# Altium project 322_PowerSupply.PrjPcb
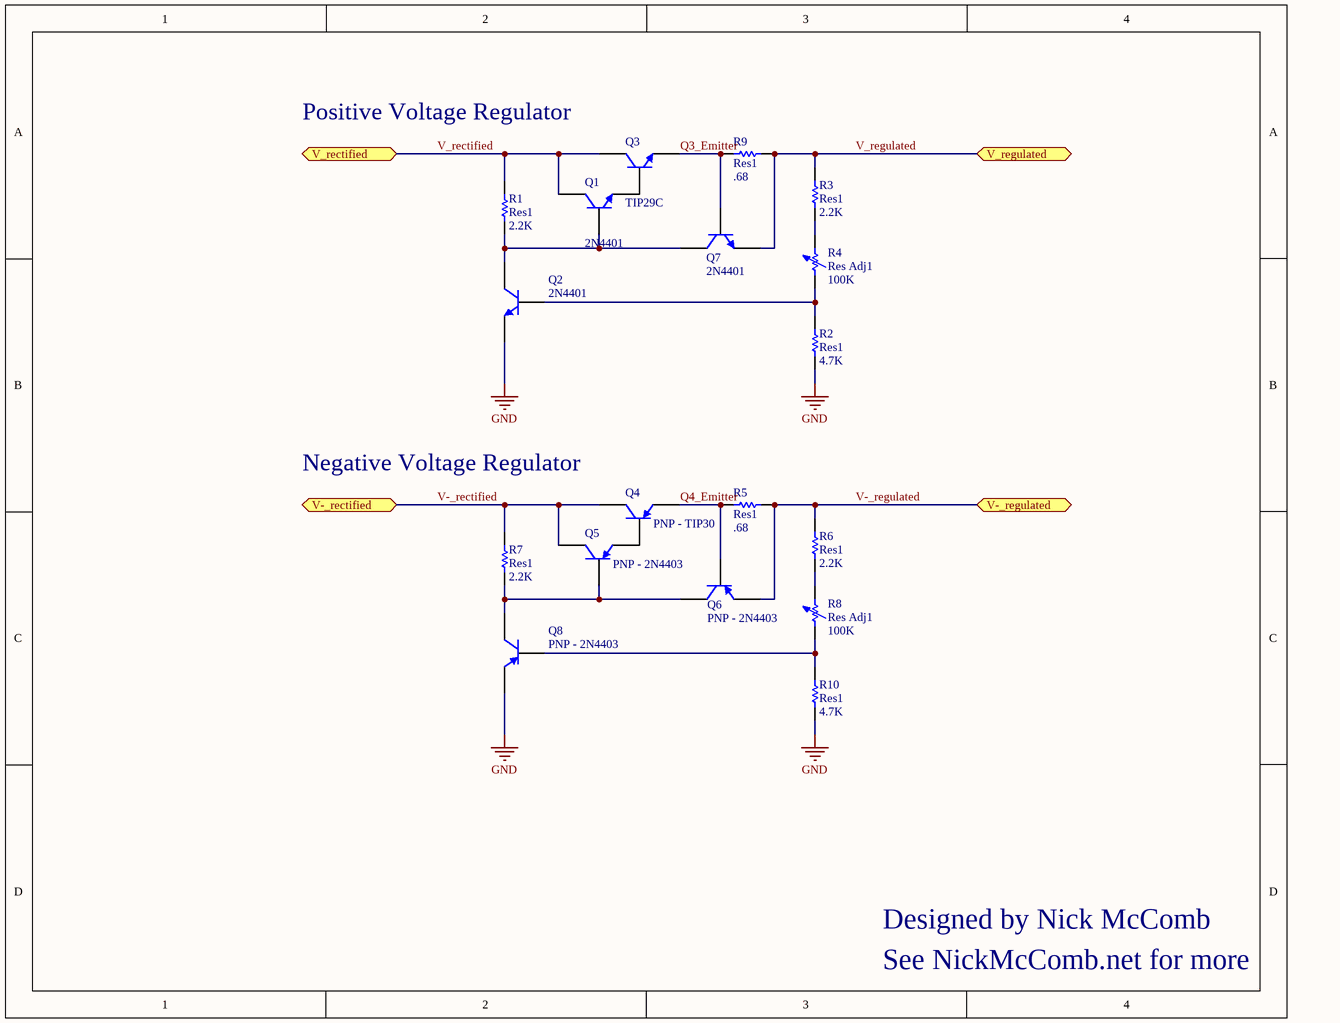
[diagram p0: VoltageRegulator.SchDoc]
2 sheets, 35 parts. Net scope: flat (ports and power ports of the same name join across sheets).
Board file: VoltageRegulator.PcbDoc
Sheets:
  VoltageRegulator.SchDoc
  Connectors.SchDoc

## Sheet VoltageRegulator.SchDoc
size A

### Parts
Q1  2N4401  [TO-92A - BJT]
Q2  2N4401  [TO-92A - BJT]
Q3  TIP29C  [TO-220AB]
Q4  PNP - TIP30  [TO-220AB]
Q5  PNP - 2N4403  [TO-92A - BJT]
Q6  PNP - 2N4403  [TO-92A - BJT]
Q7  2N4401  [TO-92A - BJT]
Q8  PNP - 2N4403  [TO-92A - BJT]
R1  Res1  value 2.2K  [AXIAL-0.3]
R2  Res1  value 4.7K  [AXIAL-0.3]
R3  Res1  value 2.2K  [AXIAL-0.3]
R4  Res Adj1  value 100K  [POT Connections]
R5  Res1  value .68  [AXIAL-0.4]
R6  Res1  value 2.2K  [AXIAL-0.3]
R7  Res1  value 2.2K  [AXIAL-0.3]
R8  Res Adj1  value 100K  [POT Connections]
R9  Res1  value .68  [AXIAL-0.4]
R10  Res1  value 4.7K  [AXIAL-0.3]

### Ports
V-_rectified, V-_regulated, V_rectified, V_regulated

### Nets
GND: Q2.3(E) Q8.3(E) R2.1 R10.1
Q3_Emitter: Q3.3(E) Q7.2(B) R9.1
Q4_Emitter: Q4.3(E) Q6.2(B) R5.1
V-_rectified: Q4.2(C) Q5.1(C) R7.2 ; port V-_rectified
V-_regulated: Q6.3(E) R5.2 R6.2 ; port V-_regulated
V_rectified: Q1.1(C) Q3.2(C) R1.2 ; port V_rectified
V_regulated: Q7.3(E) R3.2 R9.2 ; port V_regulated
NetQ1_2: Q1.2(B) Q2.1(C) Q7.1(C) R1.1
NetQ1_3: Q1.3(E) Q3.1(B)
NetQ2_2: Q2.2(B) R2.2 R4.1
NetQ4_1: Q4.1(B) Q5.3(E)
NetQ5_2: Q5.2(B) Q6.1(C) Q8.1(C) R7.1
NetQ8_2: Q8.2(B) R8.1 R10.2
NetR3_1: R3.1 R4.2
NetR6_1: R6.1 R8.2

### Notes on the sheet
- (near Q3) Positive Voltage Regulator
- (near Q4) Negative Voltage Regulator
- Designed by Nick McComb
- See NickMcComb.net for more

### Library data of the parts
Q1 Q2 Q7 = 2N4401: NPN General Purpose Amplifier
Q3 = TIP29C: NPN General Purpose Amplifier
Q4 = PNP - TIP30: PNP Bipolar Transistor
Q5 Q6 Q8 = PNP - 2N4403: PNP Bipolar Transistor
R1-R3 R5-R7 R9 R10 = Res1: Resistor
R4 R8 = Res Adj1: Variable Resistor

## Sheet Connectors.SchDoc
size A4
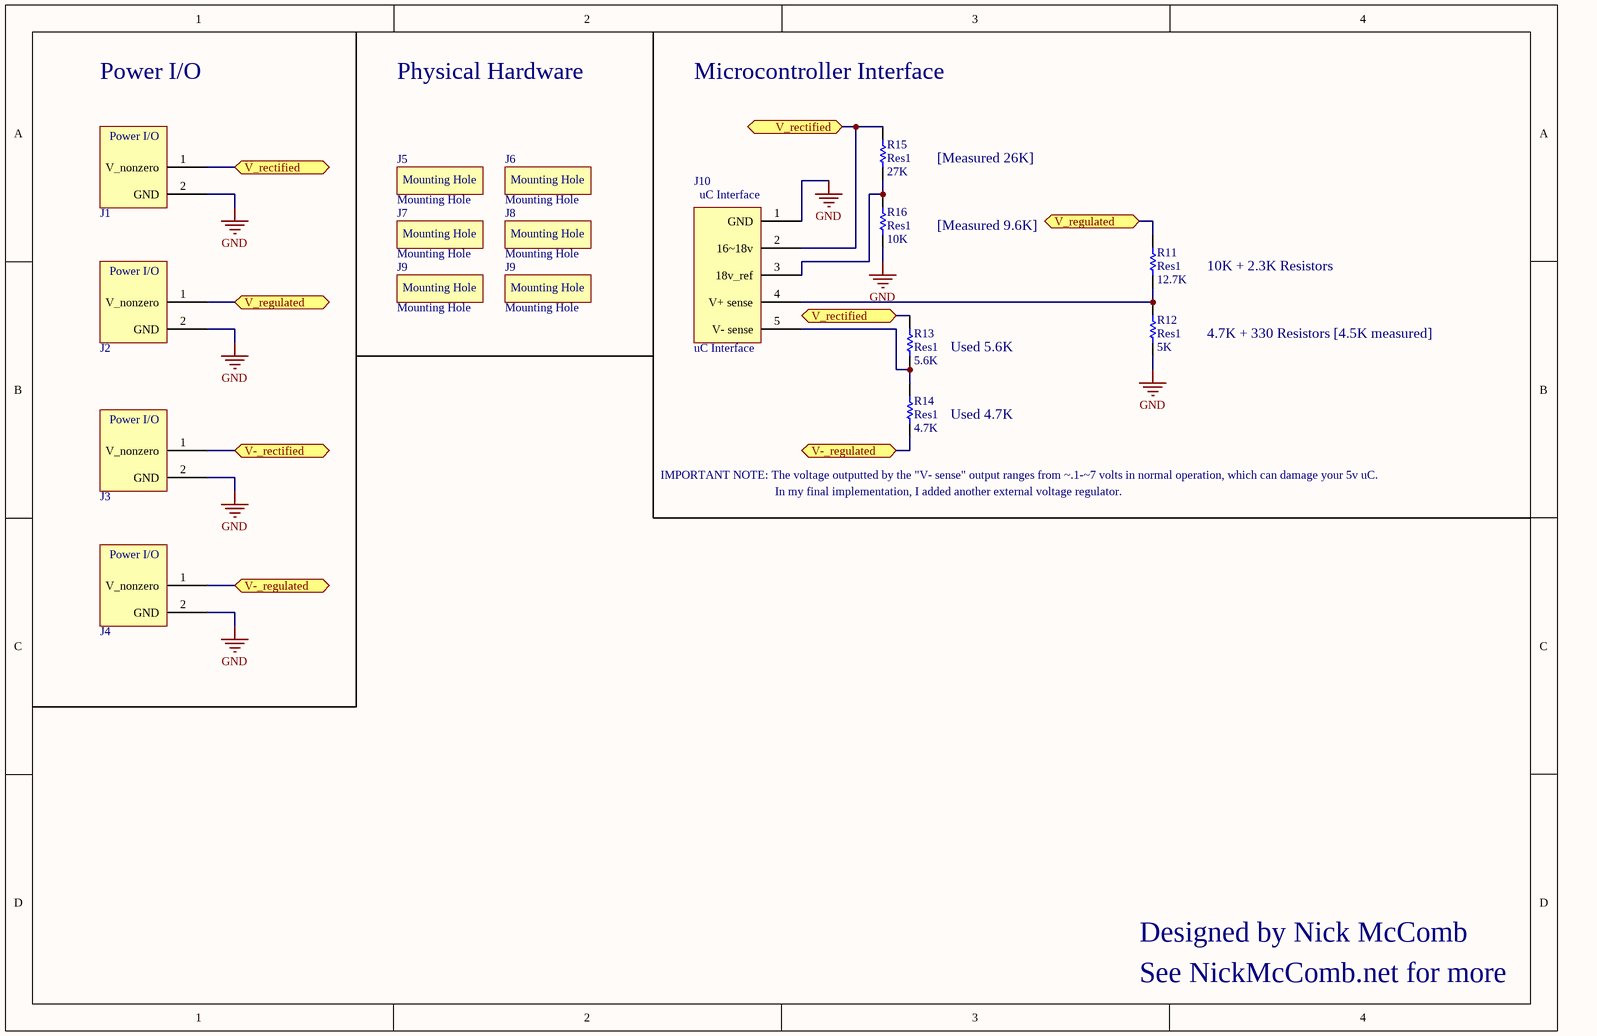
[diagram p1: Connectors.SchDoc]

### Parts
(Parts that share a designator on the sheet are numbered #1, #2 ... from top to bottom, then left to right.)
J1  Power I/O  [POWER CONNECTIONS]  (value not drawn)
J2  Power I/O  [POWER CONNECTIONS]  (value not drawn)
J3  Power I/O  [POWER CONNECTIONS]  (value not drawn)
J4  Power I/O  [POWER CONNECTIONS]  (value not drawn)
J5  Mounting Hole  [Mounting Hole]
J6  Mounting Hole  [Mounting Hole]
J7  Mounting Hole  [Mounting Hole]
J8  Mounting Hole  [Mounting Hole]
J9#1  Mounting Hole  [Mounting Hole]
J9#2  Mounting Hole  [Mounting Hole]
J10  uC Interface  [uC Interface]
R11  Res1  value 12.7K  [AXIAL-0.3]
R12  Res1  value 5K  [AXIAL-0.3]
R13  Res1  value 5.6K  [AXIAL-0.3]
R14  Res1  value 4.7K  [AXIAL-0.3]
R15  Res1  value 27K  [AXIAL-0.3]
R16  Res1  value 10K  [AXIAL-0.3]

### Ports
V-_rectified, V-_regulated, V_rectified, V_regulated

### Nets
GND: J1.2(GND) J2.2(GND) J3.2(GND) J4.2(GND) J10.1(GND) R12.1 R16.2
V-_rectified: J3.1(V_nonzero) ; port V-_rectified
V-_regulated: J4.1(V_nonzero) R14.1 ; port V-_regulated
V_rectified: J1.1(V_nonzero) J10.2(16~18v) R13.2 R15.1 ; port V_rectified
V_regulated: J2.1(V_nonzero) R11.2 ; port V_regulated
NetJ10_3: J10.3(18v_ref) R15.2 R16.1
NetJ10_4: J10.4(V+_sense) R11.1 R12.2
NetJ10_5: J10.5(V-_sense) R13.1 R14.2

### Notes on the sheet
- Power I/O
- Physical Hardware
- Microcontroller Interface
- [Measured 26K]
- [Measured 9.6K]
- 10K + 2.3K Resistors
- Used 5.6K
- 4.7K + 330 Resistors [4.5K measured]
- (near R14) Used 4.7K
- (near R14) IMPORTANT NOTE: The voltage outputted by the "V- sense" output ranges from ~.1-~7 volts in normal operation, which can damage your 5v uC.
- In my final implementation, I added another external voltage regulator.
- Designed by Nick McComb
- See NickMcComb.net for more

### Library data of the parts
R11-R16 = Res1: Resistor

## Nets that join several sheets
GND: VoltageRegulator (Q2.3 Q8.3 R2.1 R10.1), Connectors (7 pins)
V-_rectified: VoltageRegulator (Q4.2 Q5.1 R7.2), Connectors (J3.1)
V-_regulated: VoltageRegulator (Q6.3 R5.2 R6.2), Connectors (J4.1 R14.1)
V_rectified: VoltageRegulator (Q1.1 Q3.2 R1.2), Connectors (J1.1 J10.2 R13.2 R15.1)
V_regulated: VoltageRegulator (Q7.3 R3.2 R9.2), Connectors (J2.1 R11.2)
